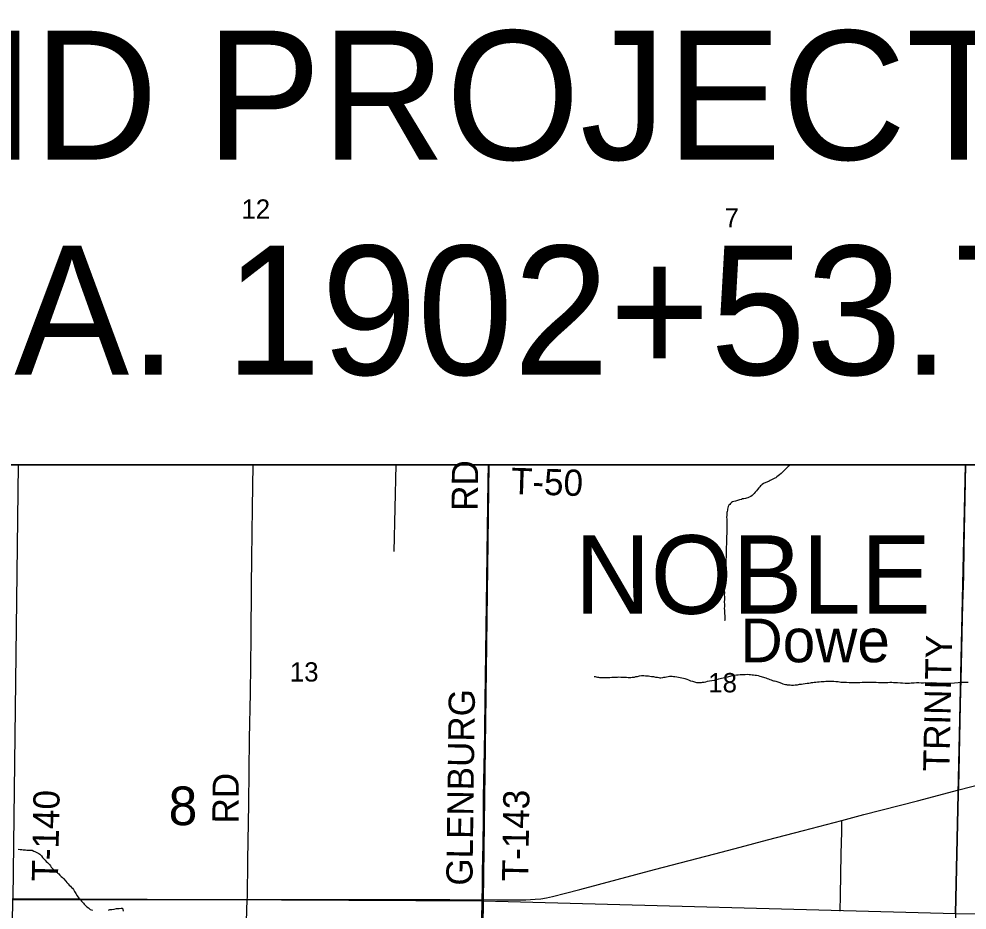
# Model space of a CAD drawing. Extents: x 2.4 to 73.1, y 4.5 to 25.6.
# Drawn here: x 33.042 to 34.07, y 23.109 to 24.076 of the extents above; entities that cross this region are included whole.
import ezdxf

# ---------------------------------------------------------------- set-up
doc = ezdxf.new("R2010")
doc.units = 0
for name, color, linetype in [('GM_X_Minor_River', 7, 'Continuous'), ('GM_X_Minor_River_Text', 7, 'Continuous'), ('GM_X_Section', 7, 'Continuous'), ('GM_X_Section_Text', 7, 'Continuous'), ('GM_X_State_Route', 7, 'Continuous'), ('GM_X_Township', 7, 'Continuous'), ('GM_X_Township_Road', 7, 'Continuous'), ('GM_X_Township_Road_Text', 7, 'Continuous'), ('GM_X_Township_Text', 7, 'Continuous'), ('SH_Text', 7, 'Continuous')]:
    doc.layers.add(name, color=color, linetype=linetype)

msp = doc.modelspace()

# ---------------------------------------------------------------- linework, layer by layer
at = {"layer": 'GM_X_Minor_River'}
msp.add_line((33.4507, 23.5921), (33.4488, 23.4982), dxfattribs=at)
for points in [[(33.8752, 23.5891), (33.8738, 23.5878), (33.8725, 23.5862), (33.8707, 23.5845), (33.8688, 23.5828), (33.8668, 23.5812), (33.8655, 23.5801), (33.8641, 23.5792), (33.8629, 23.5781), (33.8618, 23.5775), (33.8604, 23.5768), (33.8583, 23.5757), (33.857, 23.5752), (33.8556, 23.5744), (33.8497, 23.5718), (33.8483, 23.5708), (33.8474, 23.5701), (33.8464, 23.5692), (33.8456, 23.5683), (33.8446, 23.5673), (33.8431, 23.5653), (33.8419, 23.5638), (33.8405, 23.5623), (33.8393, 23.561), (33.838, 23.5597), (33.8372, 23.5588), (33.8358, 23.5577), (33.8341, 23.557), (33.8326, 23.5564), (33.8312, 23.5559), (33.8299, 23.5556), (33.8284, 23.5552), (33.827, 23.5551), (33.8259, 23.5547), (33.8234, 23.5542), (33.8215, 23.5535), (33.8194, 23.5528), (33.8175, 23.5523), (33.8161, 23.5519), (33.8148, 23.5514), (33.8138, 23.5503), (33.813, 23.5491), (33.812, 23.5482), (33.8114, 23.5469), (33.8108, 23.5454), (33.8106, 23.5439), (33.8104, 23.5428), (33.8102, 23.5416), (33.8099, 23.5405), (33.8099, 23.5392), (33.8097, 23.5373), (33.8096, 23.5354), (33.8098, 23.5333), (33.8099, 23.5308), (33.8098, 23.5289), (33.81, 23.5268), (33.8099, 23.5249), (33.8097, 23.5175), (33.8095, 23.5145), (33.8094, 23.5115), (33.8093, 23.5088), (33.8093, 23.506), (33.8092, 23.5031), (33.8091, 23.5008), (33.8091, 23.4989), (33.8092, 23.4968), (33.8092, 23.4946), (33.8091, 23.4921), (33.8089, 23.4898), (33.8088, 23.4874), (33.8089, 23.4847), (33.8089, 23.4822), (33.8086, 23.479), (33.8083, 23.4758), (33.8078, 23.472), (33.8076, 23.4694), (33.8075, 23.4669), (33.8073, 23.4642), (33.8072, 23.4614), (33.8071, 23.4586), (33.807, 23.4557), (33.8072, 23.4532), (33.8071, 23.4512), (33.8073, 23.4489), (33.8072, 23.4464), (33.8071, 23.4432), (33.8072, 23.4409), (33.8072, 23.4384), (33.8071, 23.4363), (33.8073, 23.4344), (33.8072, 23.4324), (33.8074, 23.4306), (33.8075, 23.4286), (33.8077, 23.427), (33.8078, 23.4261), (33.8078, 23.4247), (33.8078, 23.4236), (33.8078, 23.4234), (33.8078, 23.4236)], [(33.8787, 23.5921), (33.8783, 23.5917), (33.8773, 23.591), (33.8764, 23.5902), (33.8752, 23.5891)], [(33.6659, 23.3625), (33.6659, 23.3625), (33.667, 23.3623), (33.6683, 23.362), (33.6694, 23.3618), (33.6706, 23.3616), (33.6717, 23.3614), (33.6732, 23.3614), (33.6744, 23.3615), (33.6765, 23.3615), (33.6782, 23.3614), (33.6804, 23.3614), (33.6829, 23.3615), (33.6852, 23.3616), (33.6871, 23.3618), (33.6892, 23.3619), (33.6911, 23.3618), (33.6928, 23.362), (33.6949, 23.3619), (33.6968, 23.3619), (33.6995, 23.3618), (33.701, 23.3616), (33.7027, 23.3615), (33.7042, 23.3615), (33.7057, 23.3615), (33.707, 23.3616), (33.7082, 23.3618), (33.7097, 23.3619), (33.7112, 23.3623), (33.7131, 23.3626), (33.7153, 23.3631), (33.7173, 23.3635), (33.7198, 23.3636), (33.7215, 23.3633), (33.7232, 23.3633), (33.7247, 23.3631), (33.7265, 23.3628), (33.7283, 23.3626), (33.7302, 23.3624), (33.7325, 23.3619), (33.7346, 23.3617), (33.7361, 23.3615), (33.7372, 23.3612), (33.7384, 23.3612), (33.7405, 23.3615), (33.7416, 23.3617), (33.743, 23.3619), (33.7477, 23.3627), (33.7492, 23.3628), (33.7506, 23.3628), (33.7519, 23.3626), (33.7534, 23.3625), (33.7557, 23.3621), (33.7574, 23.3617), (33.7593, 23.3614), (33.761, 23.361), (33.7627, 23.3606), (33.7644, 23.3602), (33.7663, 23.3596), (33.7683, 23.3587), (33.7706, 23.3579), (33.7727, 23.3573), (33.7747, 23.3567), (33.7768, 23.3561), (33.7779, 23.3558), (33.7789, 23.3558), (33.78, 23.3558), (33.7812, 23.3559), (33.7823, 23.3561), (33.7836, 23.3563), (33.7852, 23.3564), (33.7869, 23.3567), (33.7888, 23.3573), (33.7911, 23.3576), (33.7936, 23.3581), (33.7964, 23.3586), (33.7985, 23.3591), (33.801, 23.3598), (33.8039, 23.3607), (33.8077, 23.3613), (33.8111, 23.3622), (33.8146, 23.3633), (33.8176, 23.3639), (33.8203, 23.3642), (33.8222, 23.3644), (33.8243, 23.3645), (33.8274, 23.3646), (33.8296, 23.3648), (33.8319, 23.3649), (33.834, 23.3648), (33.8355, 23.3646), (33.8372, 23.3644), (33.8389, 23.3643), (33.8406, 23.3641), (33.8421, 23.3639), (33.8437, 23.3637), (33.8455, 23.363), (33.852, 23.3612), (33.8536, 23.3604)], [(33.8536, 23.3604), (33.855, 23.3598), (33.8565, 23.3591), (33.8578, 23.3587), (33.8593, 23.3583), (33.8606, 23.3579), (33.8617, 23.3577), (33.8631, 23.3573), (33.8642, 23.3569), (33.8661, 23.3562), (33.8672, 23.356), (33.8682, 23.3556), (33.8691, 23.3552), (33.8706, 23.3546), (33.8719, 23.3542), (33.8734, 23.3538), (33.8744, 23.3538), (33.8753, 23.3535), (33.8768, 23.3535), (33.8778, 23.3533), (33.8787, 23.3533), (33.8799, 23.3532), (33.881, 23.3532), (33.8823, 23.3532), (33.8839, 23.3533), (33.8852, 23.3535), (33.8863, 23.3536), (33.8875, 23.3538), (33.8886, 23.354), (33.8907, 23.3543), (33.8926, 23.3544), (33.8947, 23.3548), (33.8968, 23.3553), (33.8987, 23.3554), (33.9004, 23.3557), (33.9018, 23.3559), (33.9031, 23.3561), (33.9046, 23.3562), (33.9064, 23.3565), (33.9081, 23.3567), (33.91, 23.3568), (33.9123, 23.357), (33.9138, 23.3569), (33.9155, 23.3571), (33.9172, 23.3574), (33.9193, 23.3575), (33.9257, 23.3574), (33.9282, 23.3571), (33.9307, 23.3569), (33.9333, 23.3564), (33.9367, 23.3563), (33.9396, 23.3563), (33.9426, 23.356), (33.9457, 23.3559), (33.9485, 23.3559), (33.9512, 23.356), (33.954, 23.3561), (33.9567, 23.3562), (33.9593, 23.3563), (33.9622, 23.3563), (33.9652, 23.3564), (33.9681, 23.3563), (33.9717, 23.3562), (33.9745, 23.3561), (33.9772, 23.3561), (33.9797, 23.356), (33.9821, 23.3561), (33.9844, 23.3561), (33.9867, 23.3562), (33.9888, 23.3562), (33.9907, 23.3561), (33.9928, 23.3561), (33.995, 23.356), (33.9981, 23.3557), (34.0005, 23.3555), (34.0032, 23.3554), (34.0051, 23.3554), (34.0066, 23.3553), (34.0079, 23.3553), (34.0097, 23.3556), (34.0112, 23.3556), (34.0131, 23.3557), (34.0155, 23.3559), (34.018, 23.3558), (34.0205, 23.3557), (34.0231, 23.3557), (34.025, 23.3558), (34.0271, 23.3557), (34.0292, 23.3557), (34.0319, 23.3558), (34.0345, 23.3557), (34.0372, 23.3557), (34.0397, 23.3554), (34.0419, 23.3552), (34.0442, 23.3551), (34.0465, 23.3551), (34.0568, 23.3556), (34.0606, 23.3558), (34.0646, 23.3563), (34.0684, 23.3564), (34.0716, 23.3565)], [(33.0414, 23.175), (33.0434, 23.1748), (33.0451, 23.1746), (33.0467, 23.1745), (33.0478, 23.1743), (33.0491, 23.1743), (33.0505, 23.1742), (33.052, 23.1742), (33.0533, 23.1742), (33.0546, 23.1741), (33.0556, 23.1741), (33.0565, 23.1739), (33.0582, 23.1731), (33.0595, 23.1725), (33.0608, 23.1719), (33.0622, 23.1711), (33.0635, 23.1703), (33.0646, 23.1697), (33.0664, 23.1678), (33.0677, 23.166), (33.0692, 23.1645), (33.0705, 23.1631), (33.0718, 23.1617), (33.0731, 23.1606), (33.0742, 23.1596), (33.0751, 23.1584), (33.0762, 23.1571), (33.0771, 23.1557), (33.0784, 23.1542), (33.0796, 23.1532), (33.0807, 23.1522), (33.0818, 23.1512), (33.0831, 23.1501), (33.0842, 23.1491), (33.0855, 23.1483), (33.0866, 23.1469), (33.0879, 23.1456), (33.0892, 23.1444), (33.0903, 23.1434), (33.0931, 23.1405), (33.0942, 23.139), (33.0955, 23.1376), (33.0966, 23.1362), (33.0979, 23.1349), (33.0992, 23.1337), (33.1003, 23.1327), (33.1014, 23.1312), (33.1025, 23.1291), (33.1038, 23.1269), (33.1052, 23.1246), (33.1069, 23.1221), (33.1087, 23.12), (33.11, 23.1186), (33.1111, 23.1176), (33.1123, 23.1165), (33.113, 23.1155), (33.1141, 23.1143), (33.1156, 23.1126), (33.1176, 23.1114), (33.1195, 23.1098), (33.1219, 23.109)], [(33.1392, 23.109), (33.1408, 23.1095), (33.1429, 23.1098), (33.1453, 23.1101), (33.148, 23.1106), (33.1507, 23.1108), (33.153, 23.1111), (33.1545, 23.111), (33.155, 23.108)]]:
    msp.add_lwpolyline(points, dxfattribs=at)
at = {"layer": 'GM_X_Section'}
for points in [[(34.0686, 23.5921), (34.0579, 23.1054), (34.5616, 23.0976), (34.5737, 23.5997), (34.3066, 23.6032), (34.3066, 23.5921)], [(33.0412, 23.5921), (33.0354, 23.1216), (33.5456, 23.119), (33.5517, 23.5921)], [(33.5517, 23.5921), (33.5456, 23.119), (34.0579, 23.1054), (34.0686, 23.5921)], [(33.5456, 23.119), (33.5389, 22.6206), (33.029, 22.6243), (33.0354, 23.1216)], [(34.0579, 23.1054), (34.0458, 22.6101), (33.5389, 22.6191), (33.5389, 22.6206), (33.5456, 23.119)]]:
    msp.add_lwpolyline(points, close=True, dxfattribs=at)
at = {"layer": 'GM_X_State_Route'}
for points in [[(33.5447, 23.1204), (33.56, 23.1202), (33.5768, 23.1201), (33.592, 23.1203), (33.6019, 23.1208), (33.6081, 23.1214), (33.6142, 23.1224), (33.6209, 23.1238), (33.6347, 23.1273), (33.6503, 23.1314), (33.7315, 23.153), (33.7967, 23.1701), (33.8243, 23.1774), (33.8538, 23.1852), (33.8929, 23.1953), (33.9347, 23.2064), (33.9584, 23.2126), (34.0165, 23.2277), (34.0613, 23.2394), (34.0881, 23.2464)], [(33.0347, 23.1207), (33.0629, 23.1207), (33.1167, 23.1206), (33.1586, 23.1206), (33.1779, 23.1205), (33.2398, 23.1206), (33.2774, 23.1206), (33.2898, 23.1206), (33.3277, 23.1207), (33.3517, 23.1206), (33.3797, 23.1205), (33.4023, 23.1206), (33.4328, 23.1205), (33.4465, 23.1205), (33.463, 23.1205), (33.4779, 23.1205), (33.4916, 23.1204), (33.5093, 23.1204), (33.5392, 23.1203), (33.5447, 23.1204)]]:
    msp.add_lwpolyline(points, dxfattribs=at)
at = {"layer": 'GM_X_Township'}
msp.add_lwpolyline([(33.5387, 22.7417), (33.5446, 23.1206), (33.5448, 23.1338), (33.545, 23.1522), (33.5451, 23.1643), (33.5455, 23.1823), (33.5458, 23.2069), (33.5461, 23.2314), (33.5463, 23.2488), (33.547, 23.2818), (33.5472, 23.3051), (33.5477, 23.3371), (33.5481, 23.3607), (33.5486, 23.3884), (33.5492, 23.4412), (33.5495, 23.467), (33.5504, 23.5233), (33.5507, 23.5478), (33.5511, 23.5755), (33.5513, 23.591), (33.5513, 23.5921), (32.7109, 23.5921)], dxfattribs=at)
at = {"layer": 'GM_X_Township_Road'}
for points in [[(33.2898, 23.1206), (33.2899, 23.1228), (33.2904, 23.1633), (33.2913, 23.2242), (33.2922, 23.2951), (33.2931, 23.3445), (33.2938, 23.4051), (33.2944, 23.4604), (33.2948, 23.4906), (33.2955, 23.5456), (33.2962, 23.5921)], [(33.5484, 23.3685), (33.5487, 23.3881), (33.5493, 23.4409), (33.5496, 23.4667), (33.5505, 23.523), (33.5508, 23.5475), (33.5512, 23.5752), (33.5514, 23.5907), (33.5514, 23.5921)], [(34.0613, 23.2394), (34.0613, 23.2429), (34.0617, 23.2587), (34.0625, 23.296), (34.0628, 23.3134), (34.0633, 23.332), (34.0644, 23.3737), (34.0652, 23.4091), (34.0659, 23.4408), (34.0667, 23.4713), (34.0673, 23.5026), (34.0681, 23.5381), (34.0688, 23.5738), (34.0691, 23.5921)], [(33.5447, 23.1204), (33.5449, 23.1335), (33.5451, 23.1519), (33.5453, 23.164), (33.5456, 23.182), (33.5459, 23.2066), (33.5462, 23.2311), (33.5465, 23.2485), (33.5471, 23.2815), (33.5474, 23.3048), (33.5478, 23.3368), (33.5482, 23.3604), (33.5484, 23.3685)], [(33.9326, 23.1079), (33.933, 23.1251), (33.9335, 23.1472), (33.9339, 23.1702), (33.9345, 23.1938), (33.9347, 23.2028), (33.9347, 23.2064)], [(33.2793, 22.7767), (33.2797, 22.782), (33.2803, 22.7898), (33.2809, 22.8022), (33.2815, 22.8156), (33.2828, 22.851), (33.2832, 22.8618), (33.2837, 22.8771), (33.2842, 22.8945), (33.2845, 22.9085), (33.2848, 22.9196), (33.285, 22.9315), (33.2853, 22.9439), (33.2859, 22.9725), (33.2862, 22.9924), (33.2865, 23.0051), (33.287, 23.0287), (33.2875, 23.0471), (33.2881, 23.0688), (33.2889, 23.0968), (33.2898, 23.1206)]]:
    msp.add_lwpolyline(points, dxfattribs=at)
at = {"layer": 'SH_Text'}
msp.add_lwpolyline([(34.3066, 24.1746), (32.7109, 24.1746), (32.7109, 23.5921), (34.3066, 23.5921)], close=True, dxfattribs=at)

# ---------------------------------------------------------------- texts
at = {"layer": 'GM_X_Minor_River_Text'}
msp.add_text('Dowe', height=0.04737, rotation=0.0384, dxfattribs=at).set_placement((33.8247, 23.3779))
at = {"layer": 'GM_X_Section_Text'}
for s, height, p in [('12', 0.02093, (33.2834, 23.8592)), ('7', 0.0209, (33.8074, 23.8497)), ('13', 0.02093, (33.3359, 23.357)), ('18', 0.02093, (33.7897, 23.3453)), ('8', 0.0419, (33.2044, 23.2012))]:
    msp.add_text(s, height=height, rotation=0, dxfattribs=at).set_placement(p)
at = {"layer": 'GM_X_Township_Road_Text'}
for s, rotation, p in [('RD', 89.5063, (33.5397, 23.5421)), ('T-50', 358.2311, (33.5754, 23.5606)), ('TRINITY', 88.7992, (34.0511, 23.2594)), ('GLENBURG', 89.2427, (33.5339, 23.1354)), ('RD', 89.5063, (33.2802, 23.2029)), ('T-140', 88.8759, (33.0844, 23.1398)), ('T-143', 89.1548, (33.5944, 23.1402))]:
    msp.add_text(s, height=0.02841, rotation=rotation, dxfattribs=at).set_placement(p)
at = {"layer": 'GM_X_Township_Text'}
msp.add_text('NOBLE', height=0.08523, rotation=0, dxfattribs=at).set_placement((33.6448, 23.4305))
at = {"layer": 'SH_Text'}
for s, p in [('END PROJECT', (32.7977, 23.9232)), ('STA. 1902+53.75', (32.7977, 23.6898))]:
    msp.add_text(s, height=0.14, rotation=360, dxfattribs=at).set_placement(p)

doc.saveas('drawing.dxf')
